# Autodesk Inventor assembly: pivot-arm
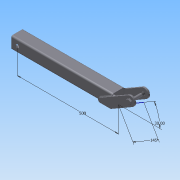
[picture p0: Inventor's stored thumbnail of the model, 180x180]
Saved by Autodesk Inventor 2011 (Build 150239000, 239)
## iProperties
Created: 2020-12
Part Number: pivot-arm
Document SubType Name: Weldment
Designer: PC
Weld Material: Welded Steel Mild
Author: PC
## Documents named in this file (3)
- C:\Users\PC\Documents\Inventor\workshop-crane-powered-by-drill\pivot-arm.iam
- C:\Users\PC\Documents\Inventor\workshop-crane-powered-by-drill\2_soporte-articulado.iam
- C:\Users\PC\Documents\Inventor\workshop-crane-powered-by-drill\pivot-arm\Design Accelerator\Bolted Connection1.iam
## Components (2 placed, 2 different names)
1. 2_soporte-articulado:1 [sub-assembly] — Mate:1, Mate:2
2. Bolted Connection:1 [sub-assembly] — Mate:1, Mate:2
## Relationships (2: Mate 2)
- Mate:1: 2_soporte-articulado:1 ↔ Bolted Connection:1
- Mate:2: 2_soporte-articulado:1 ↔ Bolted Connection:1
